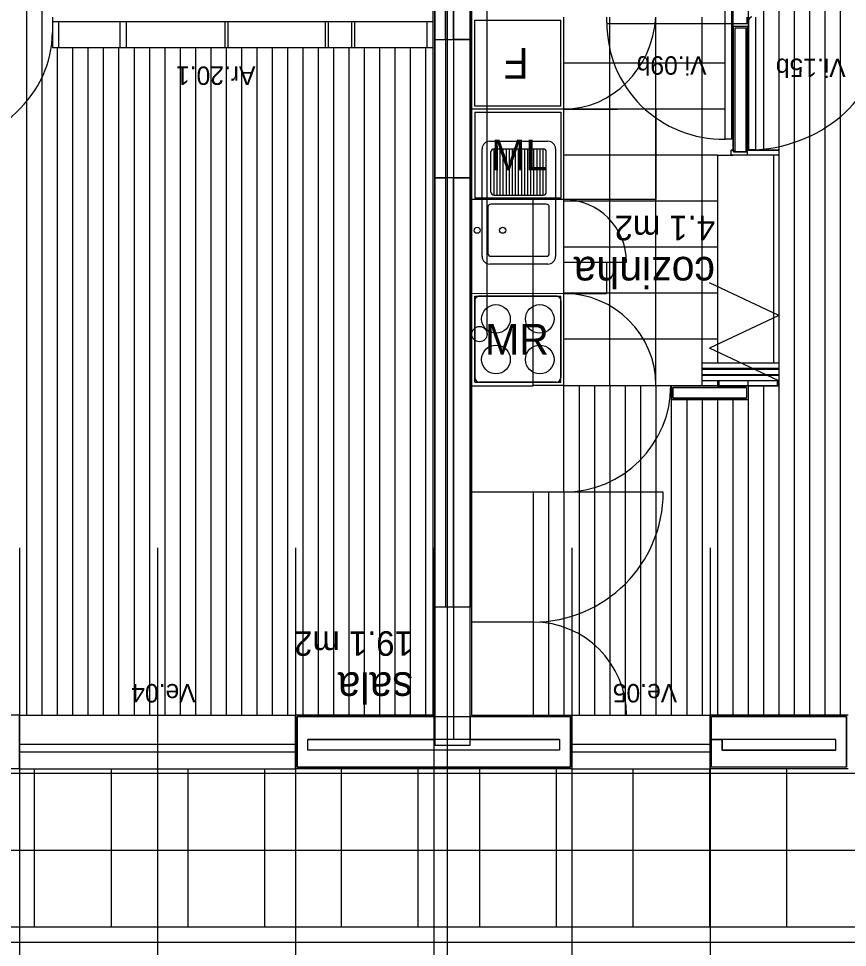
# Model space of a CAD drawing. Extents: x 1248 to 1356, y -443 to -224.
# Drawn here: x 1321.09 to 1326.49, y -248.09 to -242.03 of the extents above; entities that cross this region are included whole.
import ezdxf

# ---------------------------------------------------------------- set-up
doc = ezdxf.new("R2010")
doc.units = 0
for name, color, linetype in [('corte', 7, 'Continuous'), ('estereoctomias', 7, 'Continuous'), ('Level 1', 7, 'Continuous'), ('Level 10', 7, 'Continuous'), ('Level 11', 7, 'Continuous'), ('Level 13', 7, 'Continuous'), ('Level 2', 7, 'Continuous'), ('Level 3', 7, 'Continuous'), ('Level 4', 7, 'Continuous'), ('Level 40', 7, 'Continuous'), ('Level 60', 7, 'Continuous'), ('mob-fixo', 7, 'Continuous'), ('revestimentos', 7, 'Continuous'), ('vermelhos-cont', 7, 'Continuous'), ('vermelhos-tracej', 7, 'Continuous')]:
    doc.layers.add(name, color=color, linetype=linetype)

msp = doc.modelspace()

# ---------------------------------------------------------------- linework, layer by layer
at = {"layer": 'corte'}
for p, q in [((1325.7468, -242.892), (1325.7468, -242.902)), ((1325.8368, -242.892), (1325.8368, -242.924)), ((1324.614, -246.734), (1322.974, -246.734)), ((1326.414, -246.734), (1325.674, -246.734)), ((1324.614, -246.804), (1322.974, -246.804)), ((1326.414, -246.804), (1325.674, -246.804)), ((1324.684, -246.914), (1322.904, -246.914)), ((1326.484, -246.914), (1325.604, -246.914))]:
    msp.add_line(p, q, dxfattribs=at)
for points in [[(1324.031, -243.0713), (1323.801, -243.0713), (1323.801, -242.1713), (1324.031, -242.1713)], [(1324.031, -245.8713), (1323.801, -245.8713), (1323.801, -246.7713), (1324.031, -246.7713)]]:
    msp.add_lwpolyline(points, close=True, dxfattribs=at)
at = {"layer": 'estereoctomias'}
for points in [[(1325.1018, -240.304), (1325.1018, -241.264), (1324.9518, -241.264), (1324.9518, -240.754), (1324.0318, -240.754), (1324.0318, -242.1713), (1323.9218, -242.1713), (1323.9218, -240.304), (1324.0318, -240.304), (1324.0318, -240.604), (1324.5718, -240.604), (1324.5718, -240.304), (1324.6018, -240.304), (1324.6018, -240.604), (1325.0318, -240.604), (1325.0318, -240.304)], [(1320.626, -240.354), (1320.626, -240.424), (1323.801, -240.424), (1323.801, -242.1713), (1323.871, -242.1713), (1323.871, -240.354)], [(1325.8268, -242.094), (1325.8268, -242.902), (1325.7568, -242.902), (1325.7568, -242.094)], [(1326.0418, -242.892), (1326.0418, -242.924), (1325.7318, -242.924), (1325.7318, -242.892), (1325.7468, -242.892), (1325.7468, -242.902), (1325.8368, -242.902), (1325.8368, -242.892)], [(1323.871, -245.8713), (1323.801, -245.8713), (1323.801, -243.0713), (1323.871, -243.0713)], [(1324.031, -245.8713), (1323.9218, -245.8713), (1323.9218, -243.0713), (1324.0318, -243.0713), (1324.0318, -245.8713)], [(1325.8318, -244.4379), (1325.8318, -244.5079), (1325.3518, -244.5079), (1325.3518, -244.4379)], [(1326.0418, -244.4279), (1326.0418, -244.3959), (1325.6418, -244.3959), (1325.6418, -244.4279)], [(1324.614, -246.804), (1322.974, -246.804), (1322.974, -246.734), (1323.801, -246.734), (1323.801, -246.5953), (1323.801, -246.584), (1322.904, -246.584), (1322.904, -246.914), (1324.684, -246.914), (1324.684, -246.584), (1324.031, -246.584), (1324.031, -246.734), (1324.614, -246.734)], [(1326.484, -246.584), (1326.484, -246.914), (1325.604, -246.914), (1325.604, -246.734), (1325.674, -246.734), (1325.674, -246.804), (1326.414, -246.804), (1326.414, -246.734), (1325.604, -246.734), (1325.604, -246.584)]]:
    msp.add_lwpolyline(points, close=True, dxfattribs=at)
at = {"layer": 'Level 1'}
for p, q in [((1323.9218, -240.304), (1323.9218, -246.734)), ((1323.871, -240.354), (1323.871, -245.8713)), ((1323.801, -240.424), (1323.801, -246.584)), ((1323.801, -246.584), (1323.801, -240.424)), ((1324.0318, -246.584), (1324.0318, -241.934)), ((1325.7568, -242.902), (1325.7568, -242.094)), ((1325.7568, -242.094), (1325.8268, -242.094)), ((1325.8268, -242.094), (1325.8268, -242.902)), ((1325.7468, -242.892), (1325.7318, -242.892)), ((1325.7318, -242.924), (1325.7318, -242.892)), ((1326.0418, -242.924), (1325.7318, -242.924)), ((1325.7468, -242.902), (1325.8368, -242.902)), ((1326.0418, -242.892), (1325.8368, -242.892)), ((1326.0418, -242.892), (1326.0418, -242.924)), ((1325.8318, -244.4379), (1325.3518, -244.4379)), ((1325.3518, -244.4379), (1325.3518, -244.5079)), ((1325.6418, -244.3959), (1325.6418, -244.424)), ((1326.0418, -244.3959), (1325.6418, -244.3959)), ((1325.6418, -244.3959), (1325.6418, -244.4279)), ((1325.6518, -244.3959), (1325.6518, -244.4279)), ((1325.8318, -244.4379), (1325.8318, -244.5079)), ((1325.8418, -244.4279), (1325.8418, -244.3959)), ((1326.0418, -244.4279), (1325.8418, -244.4279)), ((1326.0318, -244.3959), (1326.0318, -244.4279)), ((1326.0418, -244.3959), (1326.0418, -244.4279)), ((1325.3518, -244.5079), (1325.8318, -244.5079)), ((1322.904, -246.584), (1324.684, -246.584)), ((1322.904, -246.914), (1322.904, -246.584)), ((1324.684, -246.584), (1324.684, -246.914)), ((1326.484, -246.584), (1325.604, -246.584)), ((1325.604, -246.914), (1325.604, -246.584)), ((1326.484, -246.914), (1326.484, -246.584)), ((1322.974, -246.804), (1322.974, -246.734)), ((1324.614, -246.734), (1324.614, -246.804)), ((1325.674, -246.804), (1325.674, -246.734)), ((1326.414, -246.804), (1326.414, -246.734))]:
    msp.add_line(p, q, dxfattribs=at)
at = {"layer": 'Level 10'}
for p, q in [((1321.141, -240.439), (1321.141, -246.574)), ((1321.241, -240.439), (1321.241, -246.574)), ((1325.7418, -240.424), (1325.7418, -242.892)), ((1325.8418, -240.424), (1325.8418, -242.892)), ((1325.9418, -240.439), (1325.9418, -242.892)), ((1326.0418, -240.439), (1326.0418, -242.892)), ((1326.1418, -240.439), (1326.1418, -246.574)), ((1326.2418, -240.439), (1326.2418, -246.574)), ((1326.3418, -240.439), (1326.3418, -246.574)), ((1326.4418, -240.439), (1326.4418, -246.574)), ((1324.9418, -244.428), (1324.9418, -242.024)), ((1325.2418, -244.428), (1325.2418, -242.024)), ((1325.5418, -244.428), (1325.5418, -242.024)), ((1321.341, -242.224), (1321.341, -246.574)), ((1321.441, -242.224), (1321.441, -246.574)), ((1321.541, -242.224), (1321.541, -246.574)), ((1321.641, -242.224), (1321.641, -246.574)), ((1321.741, -242.224), (1321.741, -246.574)), ((1321.841, -242.224), (1321.841, -246.574)), ((1321.941, -242.224), (1321.941, -246.574)), ((1322.041, -242.224), (1322.041, -246.574)), ((1322.141, -242.224), (1322.141, -246.574)), ((1322.241, -242.224), (1322.241, -246.574)), ((1322.341, -242.224), (1322.341, -246.574)), ((1322.441, -242.224), (1322.441, -246.574)), ((1322.541, -242.224), (1322.541, -246.574)), ((1322.641, -242.224), (1322.641, -246.574)), ((1322.741, -242.224), (1322.741, -246.574)), ((1322.841, -242.224), (1322.841, -246.574)), ((1322.941, -242.224), (1322.941, -246.574)), ((1323.041, -242.224), (1323.041, -246.574)), ((1323.141, -242.224), (1323.141, -246.574)), ((1323.241, -242.224), (1323.241, -246.574)), ((1323.341, -242.224), (1323.341, -246.574)), ((1323.441, -242.224), (1323.441, -246.574)), ((1323.541, -242.224), (1323.541, -246.574)), ((1323.641, -242.224), (1323.641, -246.574)), ((1323.741, -242.224), (1323.741, -246.574)), ((1325.6918, -242.324), (1324.6418, -242.324)), ((1325.6918, -242.624), (1324.6418, -242.624)), ((1325.6918, -242.624), (1324.6418, -242.624)), ((1325.6418, -242.924), (1324.6418, -242.924)), ((1325.6418, -243.224), (1324.6418, -243.224)), ((1325.6418, -243.224), (1324.6418, -243.224)), ((1325.6418, -243.524), (1324.6418, -243.524)), ((1325.6418, -243.824), (1324.6418, -243.824)), ((1325.6418, -244.124), (1324.6418, -244.124)), ((1325.3418, -244.428), (1324.6418, -244.428)), ((1324.7418, -244.428), (1324.7418, -246.574)), ((1324.8418, -244.428), (1324.8418, -246.574)), ((1324.9418, -244.428), (1324.9418, -246.574)), ((1325.0418, -244.428), (1325.0418, -246.574)), ((1325.1418, -244.428), (1325.1418, -246.574)), ((1325.2418, -244.428), (1325.2418, -246.574)), ((1325.9418, -244.4279), (1325.9418, -246.574)), ((1326.0418, -244.4279), (1326.0418, -246.574)), ((1325.3418, -244.5179), (1325.3418, -246.574)), ((1325.4418, -244.5179), (1325.4418, -246.574)), ((1325.5418, -244.5179), (1325.5418, -246.574)), ((1325.6418, -244.5179), (1325.6418, -246.574)), ((1325.7418, -244.5179), (1325.7418, -246.574)), ((1325.8418, -244.5179), (1325.8418, -246.574)), ((1324.5418, -245.121), (1324.5418, -246.574)), ((1324.6418, -245.121), (1324.6418, -246.574)), ((1318.3533, -246.954), (1323.8933, -246.954)), ((1321.1933, -247.954), (1321.1933, -246.924)), ((1321.6933, -247.954), (1321.6933, -246.924)), ((1322.1933, -247.954), (1322.1933, -246.924)), ((1322.6933, -247.954), (1322.6933, -246.924)), ((1323.1933, -247.954), (1323.1933, -246.924)), ((1323.6933, -247.954), (1323.6933, -246.924)), ((1323.8933, -246.954), (1329.2933, -246.954)), ((1324.0933, -247.954), (1324.0933, -246.924)), ((1324.5933, -247.954), (1324.5933, -246.924)), ((1325.0933, -247.954), (1325.0933, -246.924)), ((1325.5933, -247.954), (1325.5933, -246.924)), ((1326.0933, -247.954), (1326.0933, -246.924)), ((1318.3533, -247.454), (1323.8933, -247.454)), ((1323.8933, -247.454), (1329.2933, -247.454)), ((1318.3533, -247.954), (1323.8933, -247.954)), ((1323.8933, -247.954), (1329.2933, -247.954))]:
    msp.add_line(p, q, dxfattribs=at)
at = {"layer": 'Level 11'}
for p, q in [((1324.0618, -242.604), (1324.0618, -242.044)), ((1324.0618, -242.044), (1324.6218, -242.044)), ((1324.6218, -242.604), (1324.6218, -242.044)), ((1324.6218, -242.604), (1324.0618, -242.604)), ((1324.1669, -243.1651), (1324.1669, -242.9035)), ((1324.1869, -242.8835), (1324.5069, -242.8835)), ((1324.1869, -243.1851), (1324.1869, -242.8835)), ((1324.2069, -243.1851), (1324.2069, -242.8835)), ((1324.2269, -243.1851), (1324.2269, -242.8835)), ((1324.2469, -243.1851), (1324.2469, -242.8835)), ((1324.2669, -243.1851), (1324.2669, -242.8835)), ((1324.2869, -243.1851), (1324.2869, -242.8835)), ((1324.3069, -243.1851), (1324.3069, -242.8835)), ((1324.3269, -243.1851), (1324.3269, -242.8835)), ((1324.3469, -243.1851), (1324.3469, -242.8835)), ((1324.3669, -243.1851), (1324.3669, -242.8835)), ((1324.3869, -243.1851), (1324.3869, -242.8835)), ((1324.4069, -243.1851), (1324.4069, -242.8835)), ((1324.4269, -243.1851), (1324.4269, -242.8835)), ((1324.4469, -243.1851), (1324.4469, -242.8835)), ((1324.4669, -243.1851), (1324.4669, -242.8835)), ((1324.4869, -243.1851), (1324.4869, -242.8835)), ((1324.5069, -243.1851), (1324.5069, -242.8835)), ((1324.5269, -243.1651), (1324.5269, -242.9035)), ((1324.1869, -243.1851), (1324.5069, -243.1851)), ((1324.1469, -243.2635), (1324.1469, -243.5635)), ((1324.5269, -243.2435), (1324.1669, -243.2435)), ((1324.5469, -243.5635), (1324.5469, -243.2635)), ((1324.1669, -243.5835), (1324.5269, -243.5835)), ((1324.0619, -243.874), (1324.0619, -244.374)), ((1324.5919, -243.844), (1324.0919, -243.844)), ((1324.6219, -243.874), (1324.6219, -244.374)), ((1324.5919, -244.404), (1324.0919, -244.404))]:
    msp.add_line(p, q, dxfattribs=at)
for points in [[(1324.159, -242.8333), (1324.5374, -242.8333)], [(1324.109, -243.5847), (1324.109, -242.8833)], [(1324.5874, -242.8833), (1324.5874, -243.5847)], [(1324.5374, -243.6347), (1324.159, -243.6347)]]:
    msp.add_lwpolyline(points, dxfattribs=at)
for centre, radius in [((1324.0769, -243.4135), 0.0199), ((1324.2429, -243.4135), 0.0199), ((1324.1992, -243.9919), 0.0936), ((1324.4845, -243.9919), 0.0936), ((1324.1992, -244.2561), 0.0936), ((1324.4845, -244.2561), 0.0936)]:
    msp.add_circle(centre, radius, dxfattribs=at)
for centre, radius, start, end in [((1324.159, -242.8833), 0.05, 90, 180), ((1324.5374, -242.8833), 0.05, 0, 90), ((1324.1869, -242.9035), 0.02, 90, 180), ((1324.5069, -242.9035), 0.02, 0, 90), ((1324.1869, -243.1651), 0.02, 180, 270), ((1324.5069, -243.1651), 0.02, 270, 0), ((1324.1669, -243.2635), 0.02, 90, 180), ((1324.5269, -243.2635), 0.02, 0, 90), ((1324.159, -243.5847), 0.05, 180, 270), ((1324.1669, -243.5635), 0.02, 180, 270), ((1324.5269, -243.5635), 0.02, 270, 0), ((1324.5374, -243.5847), 0.05, 270, 0), ((1324.0919, -243.874), 0.03, 89.99985, 180.0002), ((1324.5919, -243.874), 0.03, 0.00009, 90.0001), ((1324.0919, -244.374), 0.03, 180.00021, 269.99999), ((1324.5919, -244.374), 0.03, 270.00005, 0.00002)]:
    msp.add_arc(centre, radius, start, end, dxfattribs=at)
at = {"layer": 'Level 13'}
for p, q in [((1325.6918, -242.819), (1325.6918, -241.924)), ((1325.7368, -242.819), (1325.7368, -241.924)), ((1325.7368, -242.819), (1325.7368, -241.924)), ((1325.7368, -242.819), (1325.7368, -241.924)), ((1321.309, -242.024), (1321.309, -242.224)), ((1321.309, -242.054), (1323.791, -242.054)), ((1321.349, -242.054), (1321.349, -242.224)), ((1321.749, -242.054), (1321.749, -242.224)), ((1321.789, -242.054), (1321.789, -242.224)), ((1322.433, -242.054), (1322.433, -242.224)), ((1322.453, -242.054), (1322.453, -242.224)), ((1323.087, -242.054), (1323.087, -242.224)), ((1323.107, -242.054), (1323.107, -242.224)), ((1323.257, -242.054), (1323.257, -242.224)), ((1323.277, -242.054), (1323.277, -242.224)), ((1323.751, -242.224), (1323.751, -242.054)), ((1324.6418, -245.121), (1324.6418, -242.024)), ((1325.8468, -242.8898), (1325.8468, -242.044)), ((1325.8918, -242.8898), (1325.8918, -242.024)), ((1323.791, -242.224), (1321.309, -242.224)), ((1324.6418, -242.624), (1324.0418, -242.624)), ((1325.7368, -242.819), (1325.6918, -242.819)), ((1325.8918, -242.8898), (1325.8468, -242.8898)), ((1326.0418, -244.2809), (1325.5418, -244.2809)), ((1325.5418, -244.3159), (1325.5418, -244.2809)), ((1326.0418, -244.3159), (1325.5418, -244.3159)), ((1326.0418, -244.3209), (1325.5418, -244.3209)), ((1325.5418, -244.3559), (1325.5418, -244.3209)), ((1326.0418, -244.3559), (1325.5418, -244.3559)), ((1326.0418, -244.3609), (1325.5418, -244.3609)), ((1325.5418, -244.3959), (1325.5418, -244.3609)), ((1325.6418, -244.3959), (1325.5418, -244.3959)), ((1324.6418, -245.121), (1324.0418, -245.121)), ((1324.4418, -245.121), (1324.4418, -246.574))]:
    msp.add_line(p, q, dxfattribs=at)
msp.add_arc((1325.8668, -242.044), 0.02, 90, 180, dxfattribs=at)
at = {"layer": 'Level 2'}
for p, q in [((1325.6418, -242.924), (1325.6418, -244.2809)), ((1325.6418, -242.924), (1325.7418, -242.924)), ((1326.0418, -242.924), (1326.0418, -244.3959)), ((1325.6418, -244.3159), (1325.6418, -244.3209)), ((1325.6418, -244.3559), (1325.6418, -244.3609)), ((1321.094, -246.574), (1322.894, -246.574)), ((1324.694, -246.574), (1325.594, -246.574)), ((1321.094, -246.764), (1322.894, -246.764)), ((1324.694, -246.764), (1325.594, -246.764)), ((1321.094, -246.814), (1322.894, -246.814)), ((1324.694, -246.814), (1325.594, -246.814)), ((1321.094, -246.924), (1322.894, -246.924)), ((1324.694, -246.924), (1325.594, -246.924)), ((1318.3533, -248.054), (1323.8933, -248.054)), ((1323.8933, -248.054), (1329.2933, -248.054))]:
    msp.add_line(p, q, dxfattribs=at)
at = {"layer": 'Level 3'}
for p, q in [((1324.6418, -243.214), (1324.0418, -243.214)), ((1324.4418, -244.424), (1324.4418, -243.214)), ((1324.4418, -244.424), (1324.6418, -244.424)), ((1324.4418, -245.968), (1324.0418, -245.968))]:
    msp.add_line(p, q, dxfattribs=at)
at = {"layer": 'Level 4'}
for p, q in [((1324.9218, -242.059), (1324.9218, -242.024)), ((1325.8368, -242.069), (1324.9218, -242.069)), ((1325.8368, -242.069), (1325.8368, -242.024)), ((1324.0618, -242.644), (1324.0618, -243.204)), ((1324.0618, -242.644), (1324.6218, -242.644)), ((1324.6218, -242.644), (1324.6218, -243.204)), ((1324.6418, -242.624), (1324.9918, -242.624)), ((1324.6418, -242.624), (1324.9918, -242.624)), ((1325.2418, -242.624), (1325.2418, -243.214)), ((1326.0068, -242.924), (1326.0068, -244.2809)), ((1324.6218, -243.204), (1324.0618, -243.204)), ((1325.2418, -243.214), (1324.6418, -243.214)), ((1324.6418, -243.622), (1325.0498, -243.622)), ((1324.9192, -243.622), (1324.9192, -243.8263)), ((1326.0418, -243.9691), (1325.5896, -243.7557)), ((1324.0418, -243.824), (1324.6418, -243.8263)), ((1324.6418, -243.8263), (1324.9192, -243.8263)), ((1324.0618, -243.844), (1324.6218, -243.844)), ((1324.0618, -244.404), (1324.0618, -243.844)), ((1324.6218, -244.404), (1324.6218, -243.844)), ((1326.0418, -243.9691), (1325.5896, -244.1825)), ((1326.0418, -244.3959), (1325.5896, -244.1825)), ((1324.0418, -244.428), (1324.4418, -244.428)), ((1324.0618, -244.404), (1324.6218, -244.404)), ((1325.2888, -245.121), (1324.4418, -245.121))]:
    msp.add_line(p, q, dxfattribs=at)
for centre, radius, start, end in [((1325.676, -242.0652), 0.7542, 179.52968, 271.19857), ((1324.6418, -243.622), 0.408, 0, 90), ((1324.6418, -244.4263), 0.6, 0.2225, 90), ((1324.6418, -244.424), 0.697, 270, 0), ((1324.4418, -245.121), 0.847, 270, 0)]:
    msp.add_arc(centre, radius, start, end, dxfattribs=at)
for centre, major_axis, ratio, start_param, end_param in [((1324.6418, -241.9731), (0, -0.6509), 0.924693, 0, 1.492592), ((1320.4256, -242.124), (-0.8834, 0), 0.869287, 1.644887, 3.141577), ((1325.8264, -242.124), (-0.8834, 0), 0.869287, 1.644887, 3.141577), ((1324.4418, -246.574), (0.6083, 0), 0.996291, 0, 1.570796)]:
    msp.add_ellipse(centre, major_axis=major_axis, ratio=ratio, start_param=start_param, end_param=end_param, dxfattribs=at)
at = {"layer": 'mob-fixo'}
for p, q in [((1324.0418, -244.091), (1324.0418, -240.604)), ((1324.1418, -244.091), (1324.1418, -240.604))]:
    msp.add_line(p, q, dxfattribs=at)
msp.add_circle((1324.0918, -244.091), 0.05, dxfattribs=at)
at = {"layer": 'revestimentos'}
for p, q in [((1323.791, -246.574), (1323.791, -240.434)), ((1324.0418, -246.574), (1324.0418, -242.024)), ((1325.7468, -242.902), (1325.7468, -242.084)), ((1325.7468, -242.084), (1325.8368, -242.084)), ((1325.8368, -242.084), (1325.8368, -242.892)), ((1325.8418, -244.4279), (1325.3418, -244.4279)), ((1325.3418, -244.4279), (1325.3418, -244.5179)), ((1325.8418, -244.4279), (1325.8418, -244.5179)), ((1325.3418, -244.5179), (1325.8418, -244.5179)), ((1321.094, -246.574), (1320.194, -246.574)), ((1321.094, -246.924), (1321.094, -246.574)), ((1323.791, -246.574), (1322.894, -246.574)), ((1322.894, -246.924), (1322.894, -246.574)), ((1324.0418, -246.574), (1324.694, -246.574)), ((1324.694, -246.574), (1324.694, -246.924)), ((1325.594, -246.924), (1325.594, -246.574)), ((1326.494, -246.574), (1325.594, -246.574)), ((1321.094, -246.924), (1320.194, -246.924)), ((1324.694, -246.924), (1322.894, -246.924)), ((1326.494, -246.924), (1325.594, -246.924))]:
    msp.add_line(p, q, dxfattribs=at)
at = {"layer": 'vermelhos-cont'}
msp.add_line((1323.884, -250.7923), (1323.884, -229.6198), dxfattribs=at)
at = {"layer": 'vermelhos-tracej'}
for p, q in [((1321.094, -245.4838), (1321.094, -250.4459)), ((1321.994, -245.4838), (1321.994, -250.4459)), ((1322.894, -245.4838), (1322.894, -250.4459)), ((1323.794, -245.4838), (1323.794, -250.4459)), ((1324.694, -245.4838), (1324.694, -250.4459)), ((1325.594, -245.4838), (1325.594, -250.4459))]:
    msp.add_line(p, q, dxfattribs=at)

# ---------------------------------------------------------------- texts
at = {"layer": 'Level 11'}
msp.add_text('F', height=0.2, rotation=180, dxfattribs=at).set_placement((1324.4133, -242.2263))
for s, p in [('ML', (1324.1678, -243.024)), ('MR', (1324.128, -244.224))]:
    msp.add_text(s, height=0.2, dxfattribs=at).set_placement(p)
at = {"layer": 'Level 40'}
for s, p in [('Vi.09b', (1325.5712, -242.2797)), ('Vi.15b', (1326.4778, -242.295)), ('Ar.20.1', (1322.6322, -242.3462)), ('Ve.04', (1322.2423, -246.3717)), ('Ve.05', (1325.3797, -246.3717))]:
    msp.add_text(s, height=0.12, rotation=180.00001, dxfattribs=at).set_placement(p)
at = {"layer": 'Level 60'}
for s, height, p in [('4.1 m2', 0.16, (1325.6266, -243.3196)), ('cozinha', 0.2, (1325.6266, -243.5874)), ('19.1 m2', 0.16, (1323.6577, -246.0279)), ('sala', 0.2, (1323.6577, -246.2957))]:
    msp.add_text(s, height=height, rotation=180, dxfattribs=at).set_placement(p)

doc.saveas('drawing.dxf')
